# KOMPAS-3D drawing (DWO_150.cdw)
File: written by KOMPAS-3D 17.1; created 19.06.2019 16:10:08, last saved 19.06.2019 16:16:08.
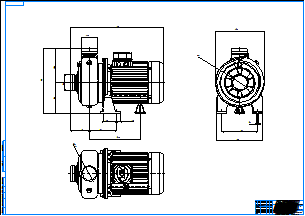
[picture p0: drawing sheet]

Sheet 1: A0, landscape

Title block, sheet 1: name: DWO_150; material: Внимание! Данный продукт является объектом авторского права ООО «Торговый Дом АДЛ». / Запрещается изменение, копирование, распространение / (в том числе путем копирования на другие сайты и ресурсы в Интернете) / или любое иное использование информации и объектов без предварительного / согласия правообладателя (ООО «Торговый Дом АДЛ»).; scale: 1:1; sheets: 1; organisation: ООО "Торговый дом АДЛ"; sheet format: A0; stored path: \\adlc.lan\data\АДЛ_ПКД\3D-модели\Поставщики\Насосное оборудование EBARA\DWO\KOMPAS 2D\DWO_150.cdw

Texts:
  user
  CONTINUOUS_RGB_0_0_0_THICK_0.18
  POLYLINE_STYLE_0.18_RGB_0_0_0
Dimensions and other numbers on the sheet: 107; 364; 198.5; 74; 50; 15; 120; 133; 253; 62.5; 193; 140; 180; 9; 57; 1:1; 1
